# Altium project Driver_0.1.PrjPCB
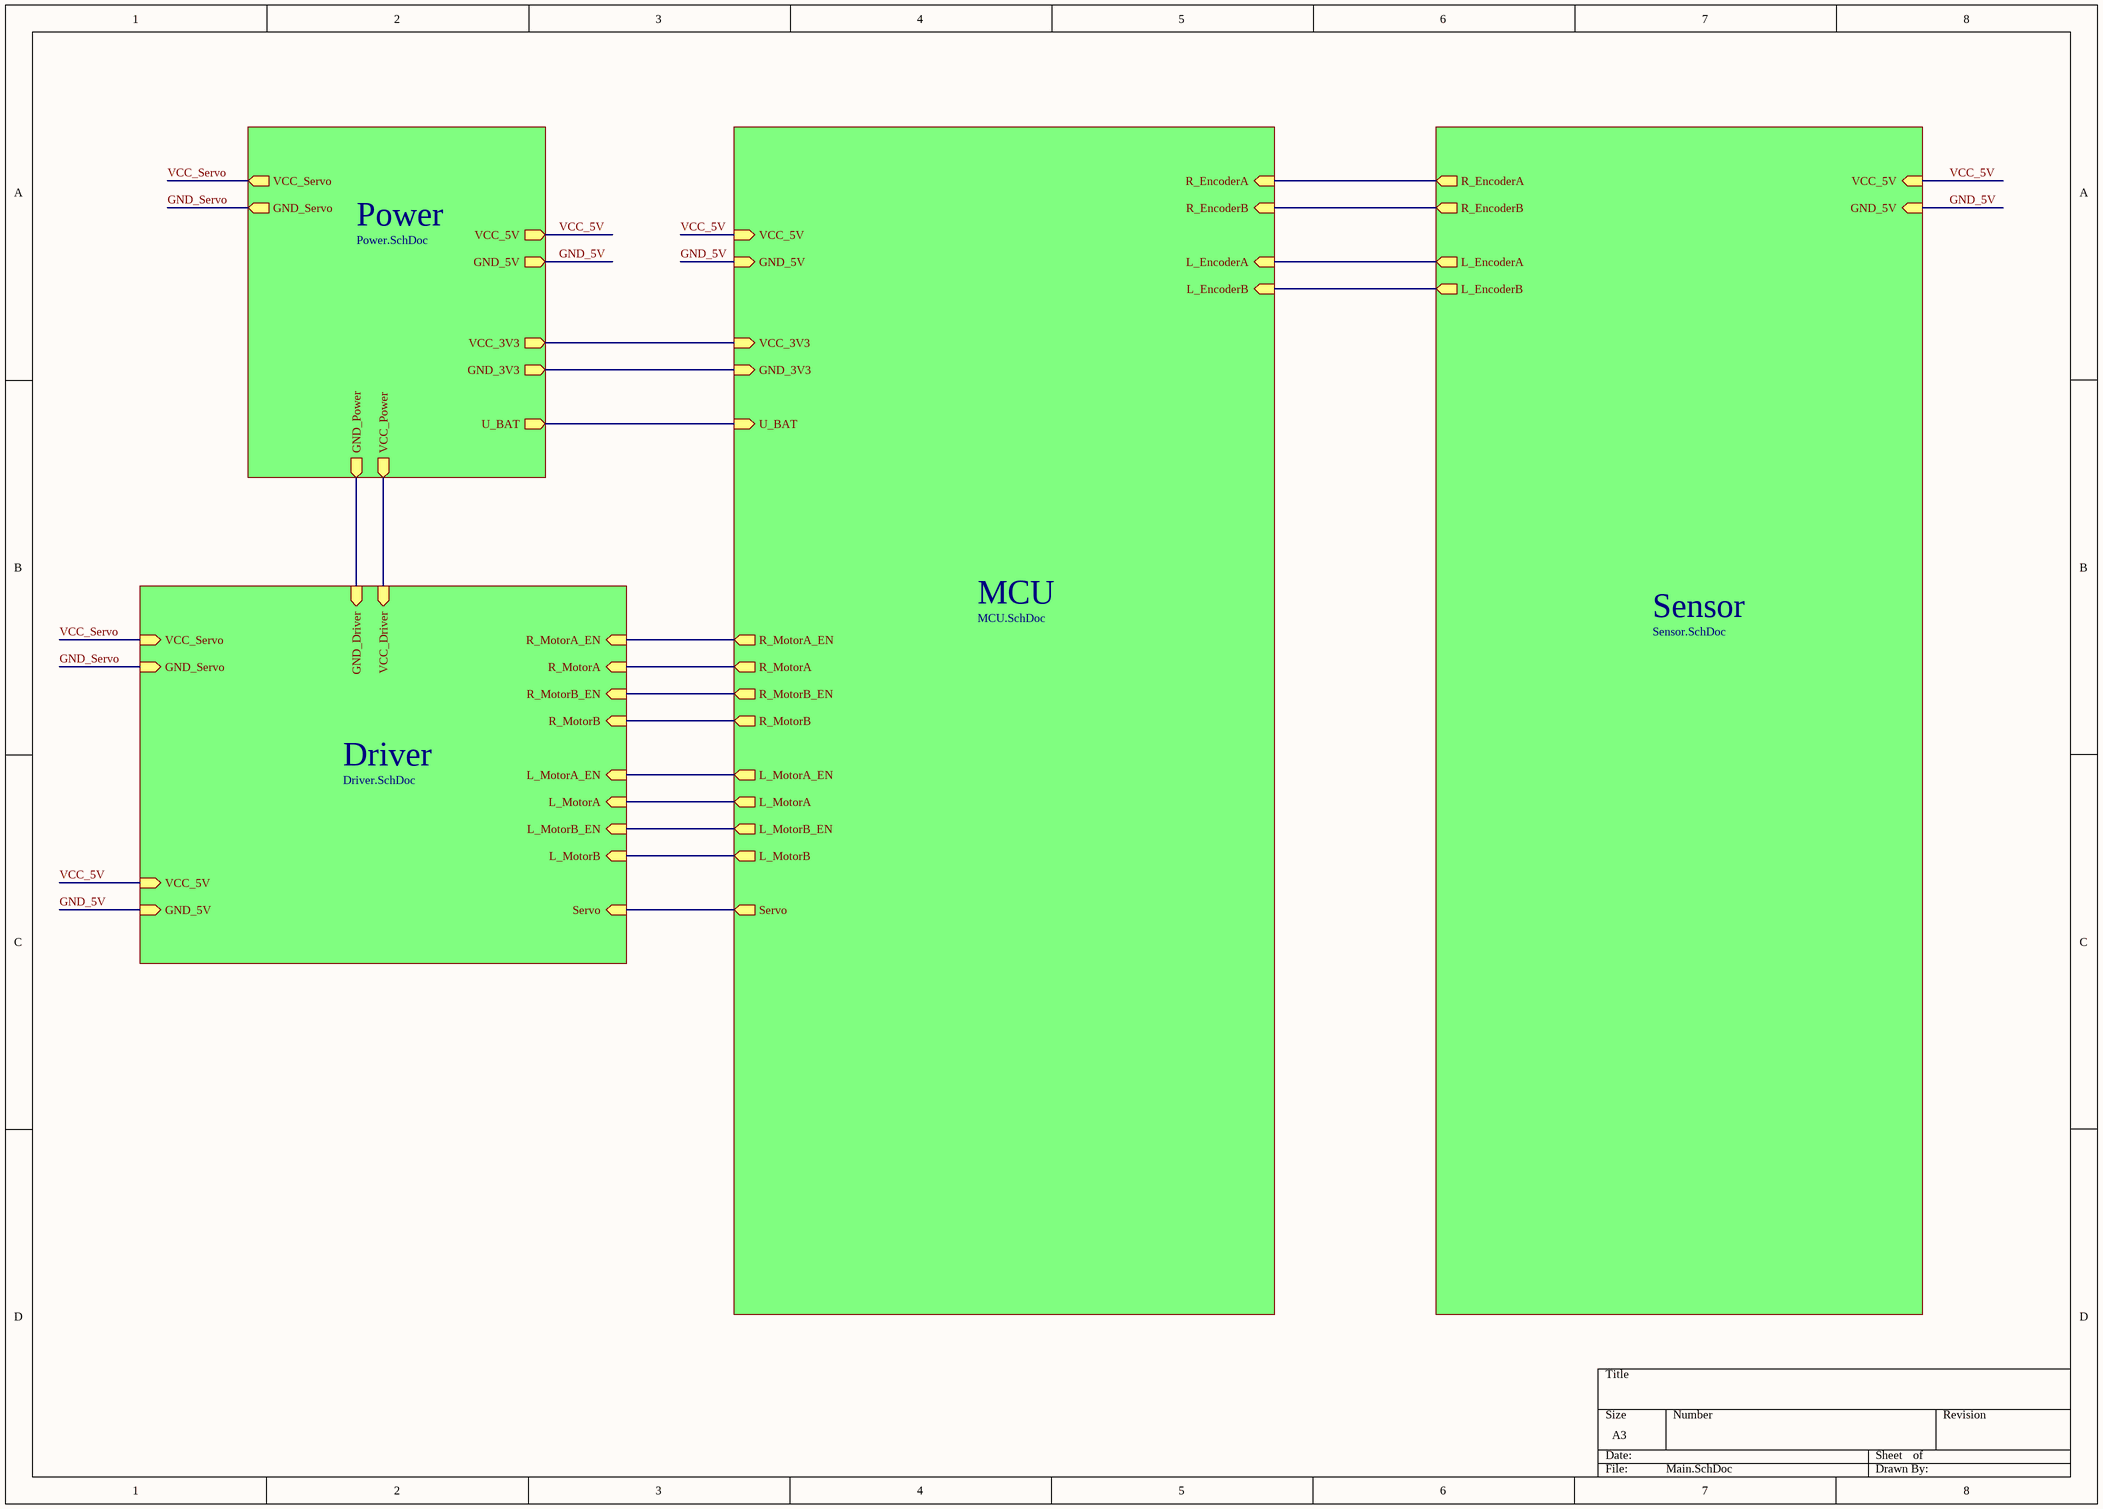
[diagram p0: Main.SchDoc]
5 sheets, 61 parts. Net scope: hierarchical (ports join the sheet entries above them; power ports are global).
Board file: PCB1.PcbDoc
Sheets:
  Main.SchDoc
    MCU = MCU.SchDoc
    Power = Power.SchDoc
    Sensor = Sensor.SchDoc
    Driver = Driver.SchDoc

## Sheet Main.SchDoc
size A3

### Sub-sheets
Driver = Driver.SchDoc: VCC_Driver (in), GND_Driver (in), R_MotorA_EN (in), R_MotorA (in), R_MotorB (in), L_MotorA_EN (in), L_MotorA (in), L_MotorB (in), Servo (in), VCC_Servo (in), GND_Servo (in), R_MotorB_EN (in), L_MotorB_EN (in), VCC_5V (in), GND_5V (in)
MCU = MCU.SchDoc: R_MotorA_EN (out), R_MotorA (out), R_MotorB (out), L_MotorA_EN (out), L_MotorA (out), L_MotorB (out), R_EncoderA (in), R_EncoderB (in), L_EncoderA (in), L_EncoderB (in), VCC_5V (in), GND_5V (in), Servo (out), U_BAT (in), VCC_3V3 (in), GND_3V3 (in), R_MotorB_EN (out), L_MotorB_EN (out)
Power = Power.SchDoc: VCC_Power (out), GND_Power (out), VCC_5V (out), GND_5V (out), VCC_Servo (out), GND_Servo (out), VCC_3V3 (out), GND_3V3 (out), U_BAT (out)
Sensor = Sensor.SchDoc: R_EncoderA (out), R_EncoderB (out), L_EncoderA (out), L_EncoderB (out), VCC_5V (in), GND_5V (in)

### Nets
GND_5V: sheet MCU/GND_5V, sheet MCU/GND_3V3, sheet Power/GND_Power, sheet Power/GND_5V, sheet Power/GND_Servo, sheet Power/GND_3V3, sheet Sensor/GND_5V, sheet Driver/GND_Driver, sheet Driver/GND_Servo, sheet Driver/GND_5V  [also labelled GND_Servo]  [project net GND_3V3]
VCC_5V: sheet MCU/VCC_5V, sheet Power/VCC_5V, sheet Sensor/VCC_5V, sheet Driver/VCC_5V
VCC_3V3: sheet MCU/VCC_3V3, sheet Power/VCC_3V3
VCC_Power: sheet Power/VCC_Power, sheet Driver/VCC_Driver
VCC_Servo: sheet Power/VCC_Servo, sheet Driver/VCC_Servo  [project net VCC_ADJ]
NetC5_1: sheet MCU/U_BAT, sheet Power/U_BAT
NetP1_1: sheet MCU/R_MotorA_EN, sheet Driver/R_MotorA_EN
NetP1_2: sheet MCU/R_MotorB_EN, sheet Driver/R_MotorB_EN
NetP1_3: sheet MCU/L_MotorA_EN, sheet Driver/L_MotorA_EN
NetP1_4: sheet MCU/L_MotorB_EN, sheet Driver/L_MotorB_EN
NetP1_5: sheet MCU/Servo, sheet Driver/Servo
NetP1_6: sheet MCU/R_EncoderB, sheet Sensor/R_EncoderB
NetP1_7: sheet MCU/L_EncoderB, sheet Sensor/L_EncoderB
NetP1_14: sheet MCU/R_MotorA, sheet Driver/R_MotorA
NetP1_15: sheet MCU/R_MotorB, sheet Driver/R_MotorB
NetP1_16: sheet MCU/L_MotorA, sheet Driver/L_MotorA
NetP1_17: sheet MCU/L_MotorB, sheet Driver/L_MotorB
NetP1_19: sheet MCU/R_EncoderA, sheet Sensor/R_EncoderA
NetP1_20: sheet MCU/L_EncoderA, sheet Sensor/L_EncoderA

## Sheet MCU.SchDoc
size A4
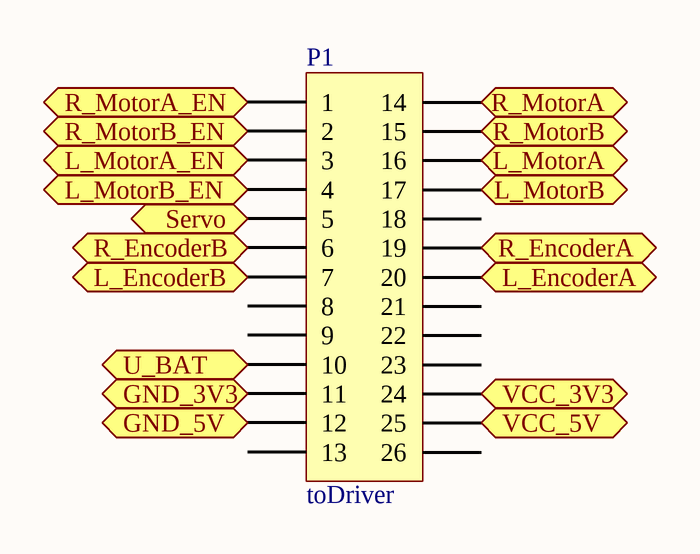
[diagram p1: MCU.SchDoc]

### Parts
P1  toDriver  [HDR2X13_CEN]

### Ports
GND_3V3 (in), GND_5V (in), L_EncoderA (in), L_EncoderB (in), L_MotorA (out), L_MotorA_EN (out), L_MotorB (out), L_MotorB_EN (out), R_EncoderA (in), R_EncoderB (in), R_MotorA (out), R_MotorA_EN (out), R_MotorB (out), R_MotorB_EN (out), Servo (out), U_BAT (in), VCC_3V3 (in), VCC_5V (in)

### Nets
GND_3V3: P1.11 P1.12 ; port GND_3V3, port GND_5V
VCC_5V: P1.25 ; port VCC_5V
VCC_3V3: P1.24 ; port VCC_3V3
NetC5_1: P1.10 ; port U_BAT
NetP1_1: P1.1 ; port R_MotorA_EN
NetP1_2: P1.2 ; port R_MotorB_EN
NetP1_3: P1.3 ; port L_MotorA_EN
NetP1_4: P1.4 ; port L_MotorB_EN
NetP1_5: P1.5 ; port Servo
NetP1_6: P1.6 ; port R_EncoderB
NetP1_7: P1.7 ; port L_EncoderB
NetP1_14: P1.14 ; port R_MotorA
NetP1_15: P1.15 ; port R_MotorB
NetP1_16: P1.16 ; port L_MotorA
NetP1_17: P1.17 ; port L_MotorB
NetP1_19: P1.19 ; port R_EncoderA
NetP1_20: P1.20 ; port L_EncoderA

Not connected (* = marked no-connect by the designer): P1 8 9 13 18 21 22 23 26

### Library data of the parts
P1 = Header 13X2A: Header, 13-Pin, Dual row

## Sheet Power.SchDoc
size A3
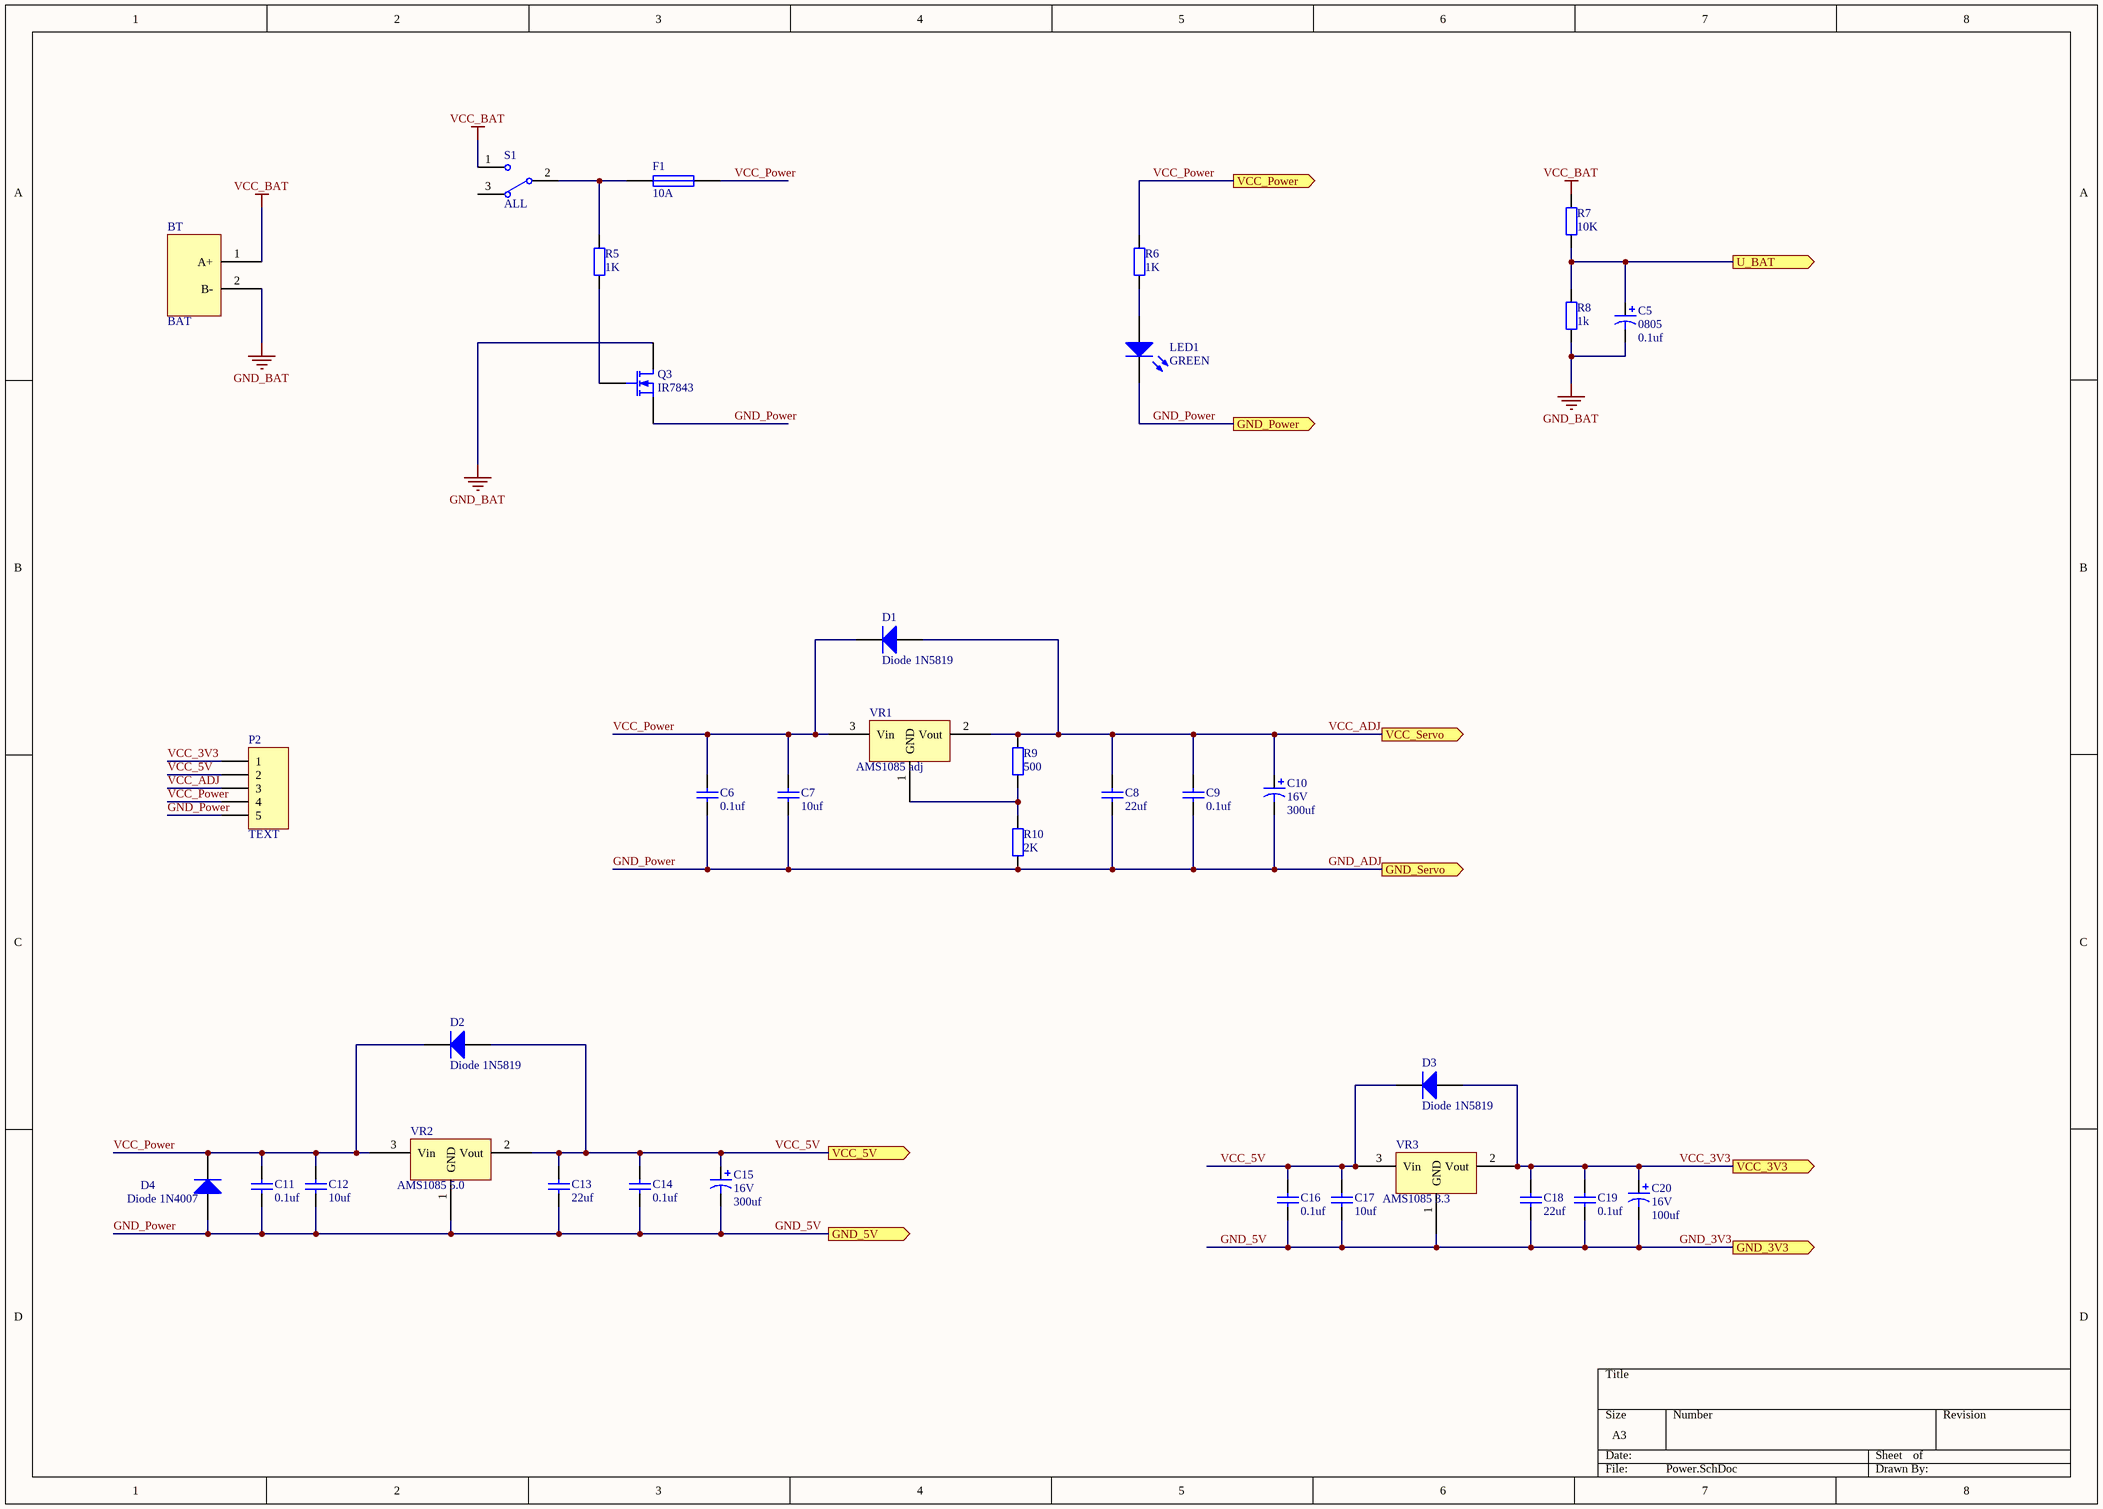
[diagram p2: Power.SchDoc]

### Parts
BT  BAT  [Header]
C5  0805  value 0.1uf  [C-RAD-0805]
C6  value 0.1uf  [C-RAD-0805]  (hidden comment: Cap)
C7  value 10uf  [C-RAD-0805]  (hidden comment: Cap)
C8  value 22uf  [C-RAD-0805]  (hidden comment: Cap)
C9  value 0.1uf  [C-RAD-0805]  (hidden comment: Cap)
C10  16V  value 300uf  [C]
C11  value 0.1uf  [C-RAD-0805]  (hidden comment: Cap)
C12  value 10uf  [C-RAD-0805]  (hidden comment: Cap)
C13  value 22uf  [C-RAD-0805]  (hidden comment: Cap)
C14  value 0.1uf  [C-RAD-0805]  (hidden comment: Cap)
C15  16V  value 300uf  [C]
C16  value 0.1uf  [C-RAD-0805]  (hidden comment: Cap)
C17  value 10uf  [C-RAD-0805]  (hidden comment: Cap)
C18  value 22uf  [C-RAD-0805]  (hidden comment: Cap)
C19  value 0.1uf  [C-RAD-0805]  (hidden comment: Cap)
C20  16V  value 100uf  [C]
D1  Diode 1N5819  [DIODE-SMB]
D2  Diode 1N5819  [DIODE-SMB]
D3  Diode 1N5819  [DIODE-SMB]
D4  Diode 1N4007  [DIO10.46-5.3x2.8]
F1  10A  [保险丝  15A]
LED1  GREEN  [LED_0805]
P2  TEXT  [HDR1X5]
Q3  IR7843  [IRLR7843]
R5  value 1K  [0603-1]  (hidden comment: Res1)
R6  value 1K  [0603-1]  (hidden comment: Res1)
R7  value 10K  [0603-1]  (hidden comment: Res1)
R8  value 1k  [0603-1]  (hidden comment: Res1)
R9  value 500  [0603-1]  (hidden comment: Res1)
R10  value 2K  [0603-1]  (hidden comment: Res1)
S1  ALL  [BK1]
VR1  AMS1085 adj  [AMS 1085CD]
VR2  AMS1085 5.0  [TO-263-3L]
VR3  AMS1085 3.3  [AMS 1085CD]

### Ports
GND_3V3 (out), GND_5V (out), GND_Power (out), GND_Servo (out), U_BAT (out), VCC_3V3 (out), VCC_5V (out), VCC_Power (out), VCC_Servo (out)

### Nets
GND_3V3: C6.1 C7.1 C8.1 C9.1 C10.2 C11.1 C12.1 C13.1 C14.1 C15.2 C16.1 C17.1 C18.1 C19.1 C20.2 D4.1(A) LED1.2(K) P2.5 Q3.3(S) R10.1 VR2.1(GND) VR3.1(GND) ; port GND_5V, port GND_3V3, port GND_Servo, port GND_Power  [also labelled GND_5V, GND_ADJ, GND_Power]
GND_BAT: BT.2(B-) C5.2 Q3.4(D) R8.1
VCC_5V: C13.2 C14.2 C15.1 C16.2 C17.2 D2.1(A) D3.2(K) P2.2 VR2.2(Vout) VR3.3(Vin) ; port VCC_5V
VCC_BAT: BT.1(A+) R7.2 S1.1
VCC_3V3: C18.2 C19.2 C20.1 D3.1(A) P2.1 VR3.2(Vout) ; port VCC_3V3
VCC_ADJ: C8.2 C9.2 C10.1 D1.1(A) P2.3 R9.2 VR1.2(Vout) ; port VCC_Servo
VCC_Power: C6.2 C7.2 C11.2 C12.2 D1.2(K) D2.2(K) D4.2(K) F1.2 P2.4 R6.2 VR1.3(Vin) VR2.3(Vin) ; port VCC_Power
NetC5_1: C5.1 R7.1 R8.2 ; port U_BAT
NetF1_1: F1.1 R5.2 S1.2
NetLED1_1: LED1.1(A) R6.1
NetQ3_1: Q3.1(G) R5.1
NetR9_1: R9.1 R10.2 VR1.1(GND)

Not connected (* = marked no-connect by the designer): S1 3

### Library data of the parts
BT = Header
C5 = Cap Pol3: Polarized Capacitor (Surface Mount)
C6-C9 C11-C14 C16-C19 = Cap: 无极性电容
C10 C15 C20 = Cap Pol1: Polarized Capacitor (Radial)
D1-D4 = Diode 1N4007: 1 Amp General Purpose Rectifier
F1 = Fuse 1: Fuse
LED1 = LED2: Typical RED, GREEN, YELLOW, AMBER GaAs LED
P2 = Header 5: Header, 5-Pin
Q3 = MOSFET-N: N-Channel MOSFET
R5-R10 = Res1: 贴片电阻
S1 = SW-SPDT: SPDT Subminiature Toggle Switch, Right Angle Mounting, Vertical Actuation
VR1-VR3 = AMS1085

## Sheet Sensor.SchDoc
size A4
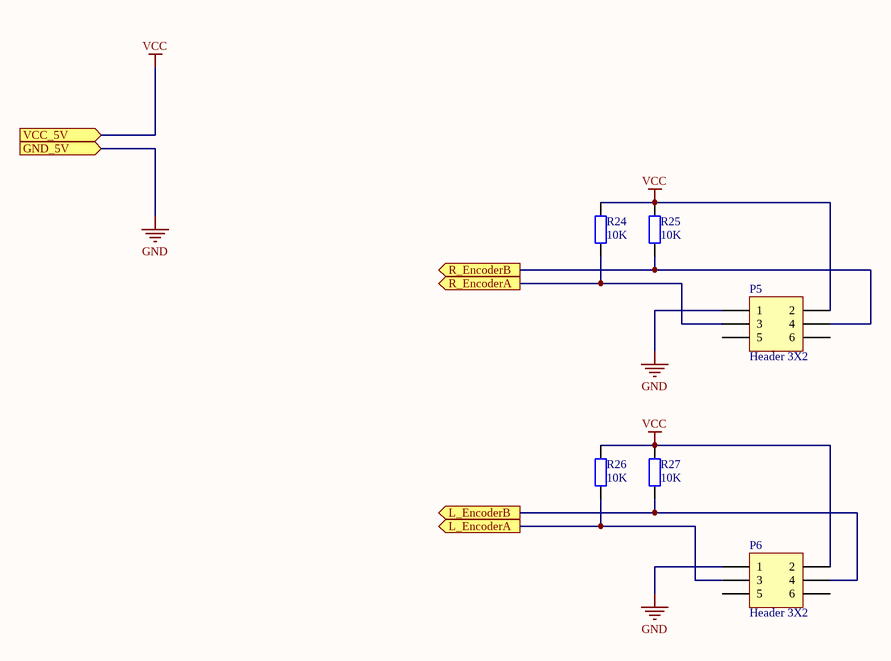
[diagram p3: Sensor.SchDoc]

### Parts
P5  Header 3X2  [HDR2X3]
P6  Header 3X2  [HDR2X3]
R24  value 10K  [0603-1]  (hidden comment: Res1)
R25  value 10K  [0603-1]  (hidden comment: Res1)
R26  value 10K  [0603-1]  (hidden comment: Res1)
R27  value 10K  [0603-1]  (hidden comment: Res1)

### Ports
GND_5V (in), L_EncoderA (out), L_EncoderB (out), R_EncoderA (out), R_EncoderB (out), VCC_5V (in)

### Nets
GND: P5.1 P6.1 ; port GND_5V  [project net GND_3V3]
VCC: P5.2 P6.2 R24.2 R25.2 R26.2 R27.2 ; port VCC_5V  [project net VCC_5V]
NetP1_6: P5.4 R25.1 ; port R_EncoderB
NetP1_7: P6.4 R27.1 ; port L_EncoderB
NetP1_19: P5.3 R24.1 ; port R_EncoderA
NetP1_20: P6.3 R26.1 ; port L_EncoderA

Not connected (* = marked no-connect by the designer): P5 5 6; P6 5 6

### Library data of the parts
P5 P6 = Header 3X2: Header, 3-Pin, Dual row
R24-R27 = Res1: 贴片电阻

## Sheet Driver.SchDoc
size A3
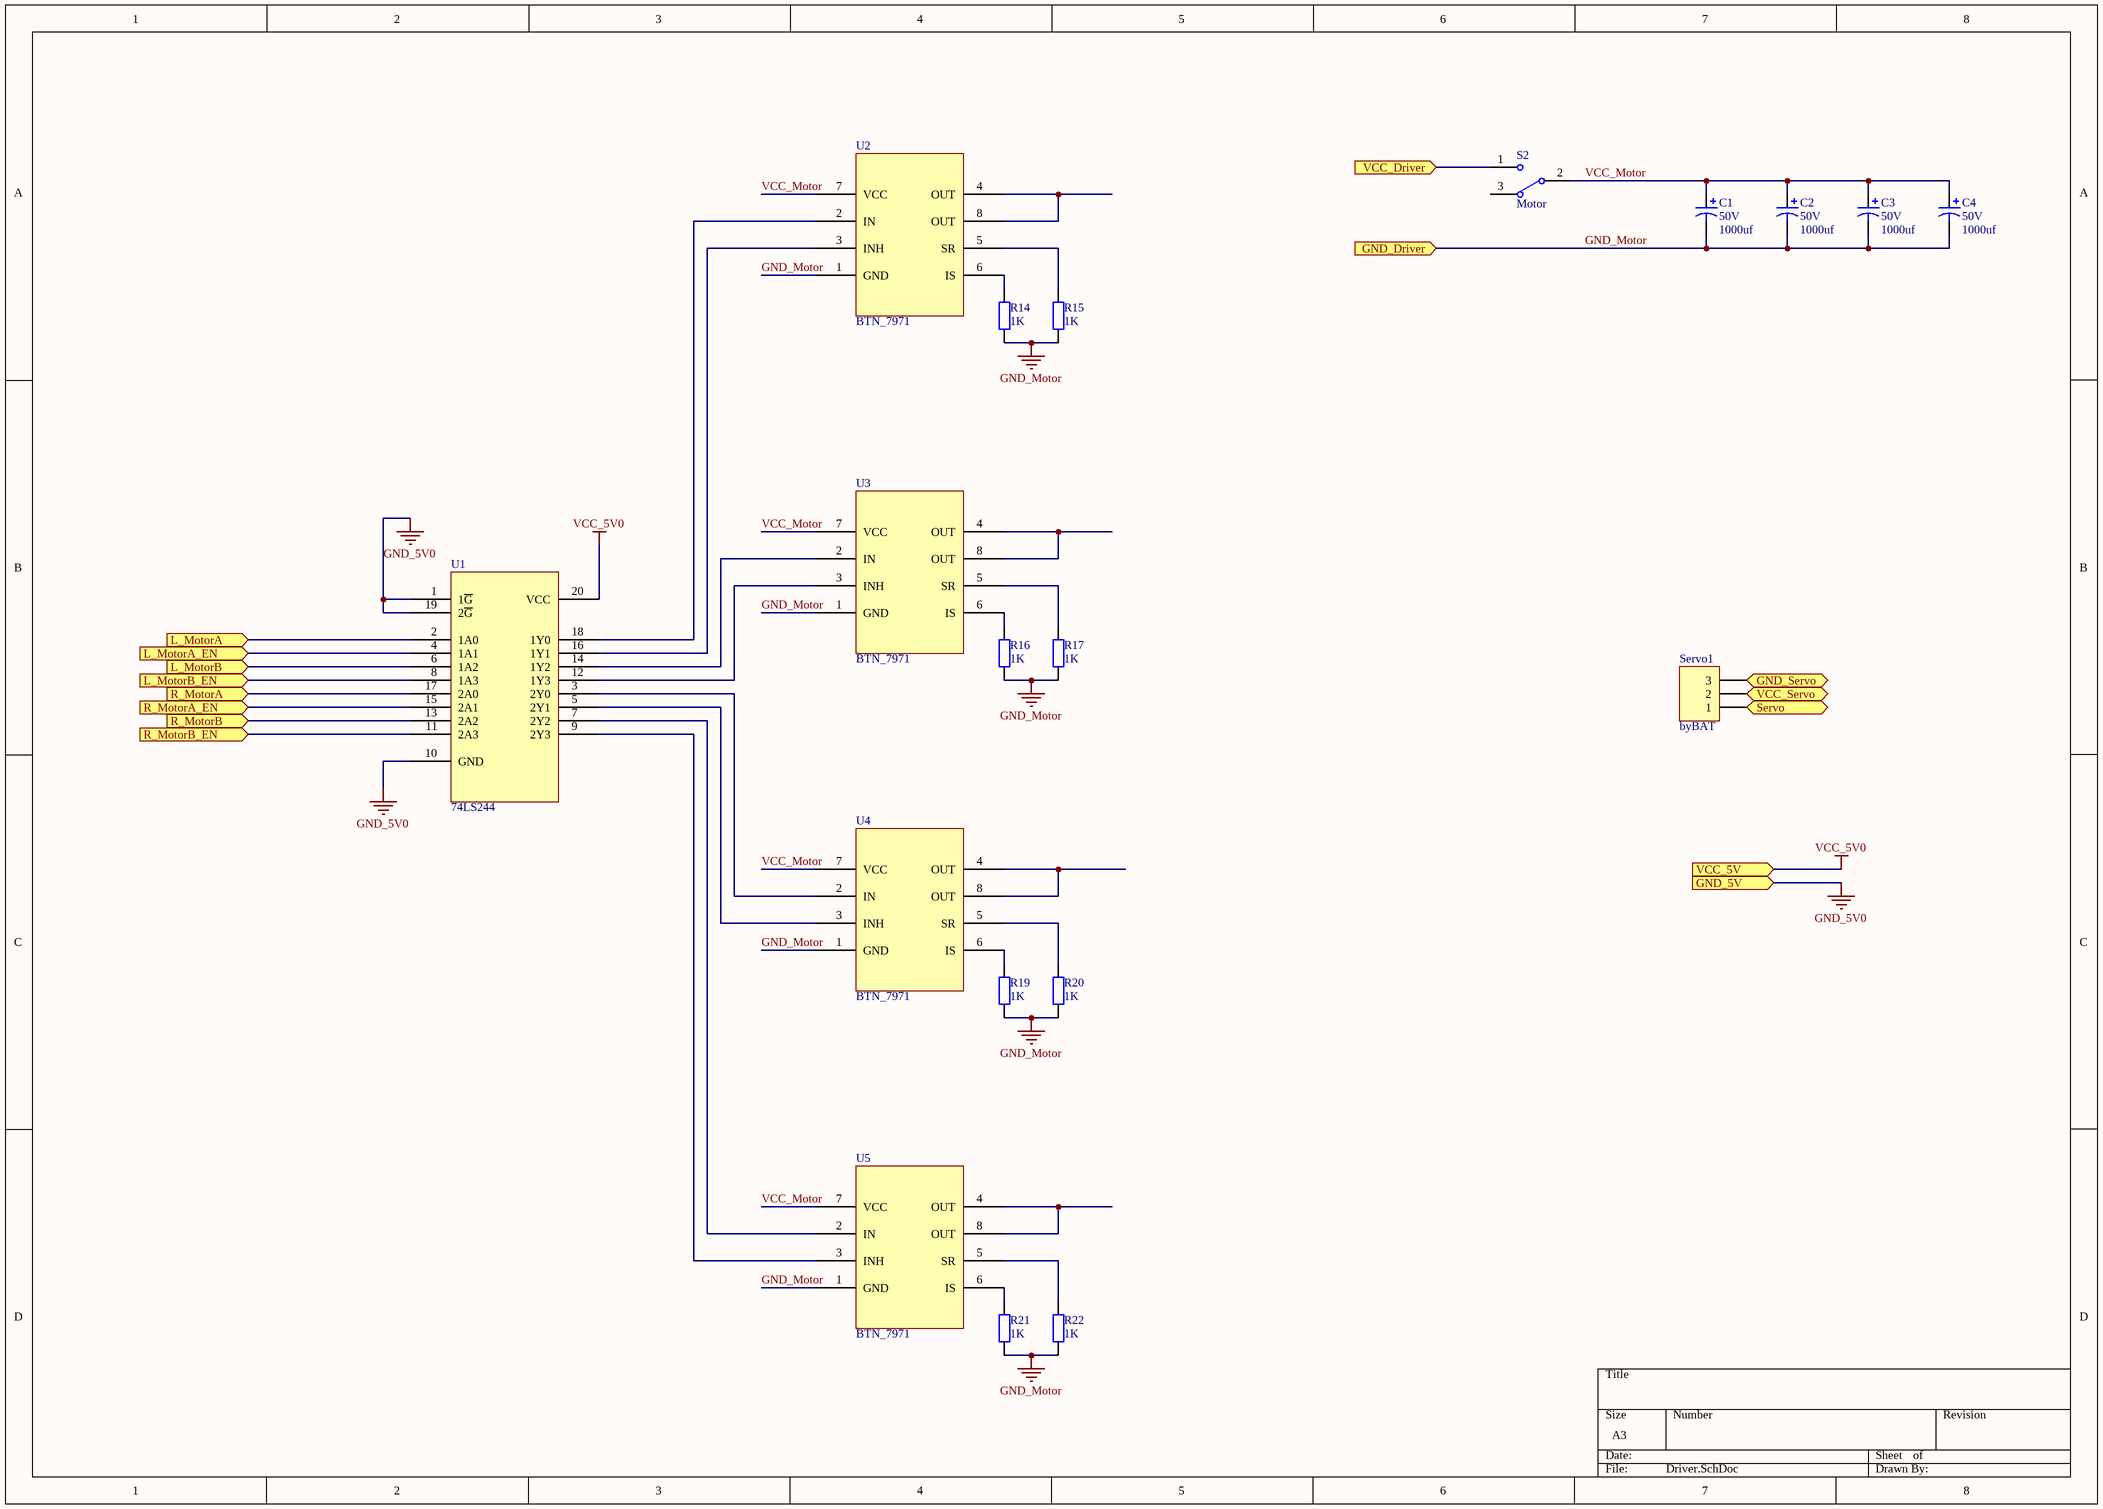
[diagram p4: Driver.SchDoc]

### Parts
C1  50V  value 1000uf  [C]
C2  50V  value 1000uf  [C]
C3  50V  value 1000uf  [C]
C4  50V  value 1000uf  [C]
R14  value 1K  [0603-1]  (hidden comment: Res1)
R15  value 1K  [0603-1]  (hidden comment: Res1)
R16  value 1K  [0603-1]  (hidden comment: Res1)
R17  value 1K  [0603-1]  (hidden comment: Res1)
R19  value 1K  [0603-1]  (hidden comment: Res1)
R20  value 1K  [0603-1]  (hidden comment: Res1)
R21  value 1K  [0603-1]  (hidden comment: Res1)
R22  value 1K  [0603-1]  (hidden comment: Res1)
S2  Motor  [BK1]
Servo1  byBAT  [HDR1X3]
U1  74LS244  [74ALS244]
U2  BTN_7971  [BTN_7971B]
U3  BTN_7971  [BTN_7971B]
U4  BTN_7971  [BTN_7971B]
U5  BTN_7971  [BTN_7971B]

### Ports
GND_5V (in), GND_Driver (in), GND_Servo (in), L_MotorA (in), L_MotorA_EN (in), L_MotorB (in), L_MotorB_EN (in), R_MotorA (in), R_MotorA_EN (in), R_MotorB (in), R_MotorB_EN (in), Servo (in), VCC_5V (in), VCC_Driver (in), VCC_Servo (in)

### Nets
GND_5V0: C1.2 C2.2 C3.2 C4.2 R14.1 R15.1 R16.1 R17.1 R19.1 R20.1 R21.1 R22.1 Servo1.3 U1.1(1~{G}) U1.10(GND) U1.19(2~{G}) U2.1(GND) U3.1(GND) U4.1(GND) U5.1(GND) ; port GND_Driver, port GND_5V, port GND_Servo  [also labelled GND_Motor]  [project net GND_3V3]
VCC_5V0: U1.20(VCC) ; port VCC_5V  [project net VCC_5V]
VCC_ADJ: Servo1.2 ; port VCC_Servo
VCC_Motor: C1.1 C2.1 C3.1 C4.1 S2.2 U2.7(VCC) U3.7(VCC) U4.7(VCC) U5.7(VCC)
VCC_Power: S2.1 ; port VCC_Driver
NetP1_1: U1.15(2A1) ; port R_MotorA_EN
NetP1_2: U1.11(2A3) ; port R_MotorB_EN
NetP1_3: U1.4(1A1) ; port L_MotorA_EN
NetP1_4: U1.8(1A3) ; port L_MotorB_EN
NetP1_5: Servo1.1 ; port Servo
NetP1_14: U1.17(2A0) ; port R_MotorA
NetP1_15: U1.13(2A2) ; port R_MotorB
NetP1_16: U1.2(1A0) ; port L_MotorA
NetP1_17: U1.6(1A2) ; port L_MotorB
NetR14_2: R14.2 U2.6(IS)
NetR15_2: R15.2 U2.5(SR)
NetR16_2: R16.2 U3.6(IS)
NetR17_2: R17.2 U3.5(SR)
NetR19_2: R19.2 U4.6(IS)
NetR20_2: R20.2 U4.5(SR)
NetR21_2: R21.2 U5.6(IS)
NetR22_2: R22.2 U5.5(SR)
NetU1_3: U1.3(2Y0) U4.2(IN)
NetU1_5: U1.5(2Y1) U4.3(INH)
NetU1_7: U1.7(2Y2) U5.2(IN)
NetU1_9: U1.9(2Y3) U5.3(INH)
NetU1_12: U1.12(1Y3) U3.3(INH)
NetU1_14: U1.14(1Y2) U3.2(IN)
NetU1_16: U1.16(1Y1) U2.3(INH)
NetU1_18: U1.18(1Y0) U2.2(IN)
NetU2_4: U2.4(OUT) U2.8(OUT)
NetU3_4: U3.4(OUT) U3.8(OUT)
NetU4_4: U4.4(OUT) U4.8(OUT)
NetU5_4: U5.4(OUT) U5.8(OUT)

Not connected (* = marked no-connect by the designer): S2 3

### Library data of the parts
C1-C4 = Cap Pol1: Polarized Capacitor (Radial)
R14-R17 R19-R22 = Res1: 贴片电阻
S2 = SW-SPDT: as S1 on sheet Power
Servo1 = Header 3: Header, 3-Pin

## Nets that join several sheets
GND_3V3: MCU (P1.11 P1.12), Power (22 pins), Sensor (P5.1 P6.1), Driver (20 pins)
VCC_5V: MCU (P1.25), Power (10 pins), Sensor (6 pins), Driver (U1.20)
NetC5_1: MCU (P1.10), Power (C5.1 R7.1 R8.2)
NetP1_1: MCU (P1.1), Driver (U1.15)
NetP1_2: MCU (P1.2), Driver (U1.11)
NetP1_3: MCU (P1.3), Driver (U1.4)
NetP1_4: MCU (P1.4), Driver (U1.8)
NetP1_5: MCU (P1.5), Driver (Servo1.1)
NetP1_6: MCU (P1.6), Sensor (P5.4 R25.1)
NetP1_7: MCU (P1.7), Sensor (P6.4 R27.1)
NetP1_14: MCU (P1.14), Driver (U1.17)
NetP1_15: MCU (P1.15), Driver (U1.13)
NetP1_16: MCU (P1.16), Driver (U1.2)
NetP1_17: MCU (P1.17), Driver (U1.6)
NetP1_19: MCU (P1.19), Sensor (P5.3 R24.1)
NetP1_20: MCU (P1.20), Sensor (P6.3 R26.1)
VCC_3V3: MCU (P1.24), Power (6 pins)
VCC_ADJ: Power (7 pins), Driver (Servo1.2)
VCC_Power: Power (12 pins), Driver (S2.1)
